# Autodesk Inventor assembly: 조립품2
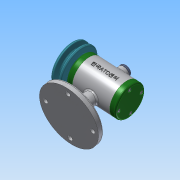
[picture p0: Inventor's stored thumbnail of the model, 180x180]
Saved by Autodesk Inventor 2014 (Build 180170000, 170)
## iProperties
Created: 2018-12
Part Number: 조립품2
Document SubType Name: Assembly
Designer: 601-06
Author: 601-06
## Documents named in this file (15)
- C:\Users\601-06\Desktop\조립품2.iam
- C:\Users\601-06\AppData\Local\Microsoft\Windows\Temporary Internet Files\Content.IE5\UWTW91T4\V벨트풀리[1].ipt
- C:\Users\601-06\AppData\Local\Microsoft\Windows\Temporary Internet Files\Content.IE5\2FEDIC85\고무캡[1].ipt
- C:\Users\601-06\AppData\Local\Microsoft\Windows\Temporary Internet Files\Content.IE5\KZTJY1WX\너트_M8[1].ipt
- 너트 M8.ipt
- C:\Users\601-06\AppData\Local\Microsoft\Windows\Temporary Internet Files\Content.IE5\UWTW91T4\뒤커버[1].ipt
- C:\Users\601-06\AppData\Local\Microsoft\Windows\Temporary Internet Files\Content.IE5\2FEDIC85\베어링_15_x_32_x_9[1].ipt
- C:\Users\601-06\AppData\Local\Microsoft\Windows\Temporary Internet Files\Content.IE5\KZTJY1WX\볼트_M4_x_12[1].ipt
- C:\Users\601-06\AppData\Local\Microsoft\Windows\Temporary Internet Files\Content.IE5\UWTW91T4\스프링와셔_8[1].ipt
- C:\Users\601-06\AppData\Local\Microsoft\Windows\Temporary Internet Files\Content.IE5\2FEDIC85\앞커버[1].ipt
- C:\Users\601-06\AppData\Local\Microsoft\Windows\Temporary Internet Files\Content.IE5\KZTJY1WX\오일_실_15_25_7[1].ipt
- C:\Users\601-06\AppData\Local\Microsoft\Windows\Temporary Internet Files\Content.IE5\UWTW91T4\와셔_8x17[1].ipt
- C:\Users\601-06\AppData\Local\Microsoft\Windows\Temporary Internet Files\Content.IE5\2FEDIC85\축[1].ipt
- C:\Users\601-06\AppData\Local\Microsoft\Windows\Temporary Internet Files\Content.IE5\KZTJY1WX\키_3_x_3_x_12[1].ipt
- C:\Users\601-06\Desktop\부품1.ipt
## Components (2 placed, 2 different names)
1. V벨트풀리[1]:1
2. 고무캡[1]:1
